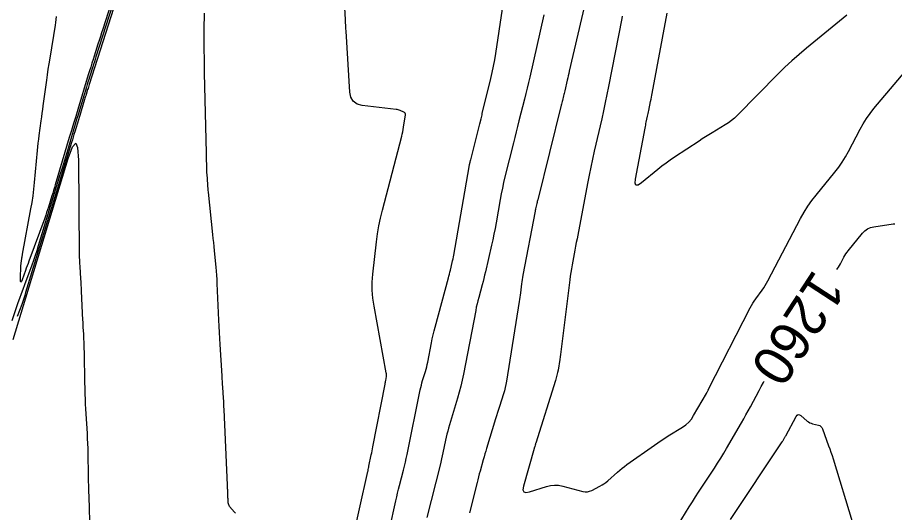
# Model space of a CAD drawing. Extents: x 658976 to 668726, y 639543 to 647196.
# Drawn here: x 661560 to 661691.9, y 641060.1 to 641134.6 of the extents above; entities that cross this region are included whole.
import ezdxf

# ---------------------------------------------------------------- set-up
doc = ezdxf.new("R2010")
doc.units = 0
for name, color, linetype in [('Ex_Contour Labels', 7, 'Continuous'), ('Ex_Major Contours', 7, 'Continuous'), ('Ex_Minor Contours', 7, 'Continuous')]:
    doc.layers.add(name, color=color, linetype=linetype)

msp = doc.modelspace()

# ---------------------------------------------------------------- linework, layer by layer
at = {"layer": 'Ex_Major Contours'}
for points in [[(661645.55, 641137.76), (661642.97, 641126.54), (661642.89, 641126.21), (661642.81, 641125.87), (661642.74, 641125.54), (661642.66, 641125.21), (661642.29, 641123.58), (661642.25, 641123.4), (661642.21, 641123.22), (661642.16, 641123.04), (661642.12, 641122.86), (661641.94, 641122.14), (661641.89, 641121.97), (661641.85, 641121.79), (661641.8, 641121.61), (661641.76, 641121.43), (661638.23, 641107.21), (661638.19, 641107.07), (661638.16, 641106.93), (661638.13, 641106.78), (661638.09, 641106.64), (661637.91, 641105.85), (661637.9, 641105.82), (661637.9, 641105.79), (661637.89, 641105.76), (661637.89, 641105.73), (661637.86, 641105.58), (661637.84, 641105.49), (661636.01, 641095.86), (661635.95, 641095.53), (661635.9, 641095.2), (661635.85, 641094.87), (661635.8, 641094.54), (661635.64, 641093.21), (661635.6, 641092.87), (661635.55, 641092.54), (661635.5, 641092.21), (661635.45, 641091.88), (661633.52, 641079.92), (661633.44, 641079.43), (661633.33, 641078.95), (661633.21, 641078.47), (661633.07, 641078), (661632.48, 641076.11), (661632.33, 641075.64), (661632.18, 641075.17), (661632.03, 641074.69), (661631.89, 641074.22), (661630.54, 641069.8), (661630.41, 641069.38), (661630.29, 641068.95), (661630.16, 641068.52), (661630.04, 641068.09), (661629.55, 641066.37), (661629.44, 641065.94), (661629.32, 641065.51), (661629.21, 641065.07), (661629.1, 641064.64), (661627.97, 641060.08)], [(661559.33, 641086.19), (661567.64, 641113.39), (661568.28, 641115.17), (661568.75, 641115.73), (661569.04, 641115.06), (661569.15, 641113.17), (661569.28, 641099.04), (661569.29, 641098.57), (661569.31, 641098.11), (661569.33, 641097.64), (661569.35, 641097.18), (661569.48, 641095.32), (661569.51, 641094.85), (661569.54, 641094.39), (661569.56, 641093.92), (661569.58, 641093.46), (661569.79, 641089.09), (661569.8, 641088.83), (661569.81, 641088.56), (661569.83, 641088.3), (661569.84, 641088.03), (661569.91, 641086.97), (661569.92, 641086.7), (661569.93, 641086.44), (661569.94, 641086.17), (661569.95, 641085.9), (661570.13, 641077.95), (661570.15, 641077.21), (661570.18, 641076.46), (661570.22, 641075.72), (661570.26, 641074.98), (661570.45, 641072.01), (661570.49, 641071.26), (661570.52, 641070.52), (661570.55, 641069.78), (661570.57, 641069.03), (661570.62, 641065.73), (661570.64, 641064.93), (661570.66, 641064.13), (661570.68, 641063.33), (661570.7, 641062.53), (661570.85, 641057.04)], [(661683.21, 641096.69), (661683.31, 641096.84), (661683.46, 641097.08), (661683.61, 641097.32), (661683.75, 641097.58), (661684.28, 641098.59), (661684.42, 641098.84), (661684.57, 641099.08), (661684.74, 641099.32), (661684.91, 641099.54), (661687.09, 641102.18), (661687.44, 641102.54), (661687.84, 641102.82), (661688.28, 641103.02), (661688.77, 641103.14), (661691.67, 641103.58), (661691.76, 641103.59), (661691.84, 641103.6), (661691.92, 641103.6)], [(661658.26, 641056.46), (661661.02, 641061.01), (661661.48, 641061.75), (661661.94, 641062.49), (661662.41, 641063.22), (661662.89, 641063.95), (661664.81, 641066.84), (661665.28, 641067.57), (661665.75, 641068.3), (661666.2, 641069.05), (661666.64, 641069.79), (661668.86, 641073.66), (661669.2, 641074.26), (661669.54, 641074.86), (661669.87, 641075.46), (661670.2, 641076.06), (661671.52, 641078.49), (661671.85, 641079.09), (661672.17, 641079.7), (661672.29, 641079.93)]]:
    msp.add_lwpolyline(points, dxfattribs=at)
at = {"layer": 'Ex_Minor Contours'}
for points in [[(661580.99, 641156.54), (661570.78, 641124.53), (661570.72, 641124.34), (661570.66, 641124.15), (661570.6, 641123.97), (661570.54, 641123.78), (661570.3, 641123.04), (661570.25, 641122.85), (661570.19, 641122.66), (661570.13, 641122.48), (661570.07, 641122.29), (661569.56, 641120.59), (661569.46, 641120.25), (661569.35, 641119.9), (661569.25, 641119.56), (661569.15, 641119.21), (661568.62, 641117.45), (661568.49, 641117.04), (661568.37, 641116.63), (661568.25, 641116.22), (661568.12, 641115.82), (661561.22, 641093.23), (661561.08, 641092.79), (661560.94, 641092.34), (661560.78, 641091.9), (661560.63, 641091.46), (661559.96, 641089.64)], [(661578.27, 641148.98), (661571.8, 641128.71), (661571.68, 641128.33), (661571.56, 641127.95), (661571.44, 641127.57), (661571.32, 641127.19), (661570.83, 641125.67), (661570.71, 641125.29), (661570.59, 641124.91), (661570.47, 641124.53), (661570.36, 641124.15), (661569.32, 641120.69), (661569.1, 641119.99), (661568.89, 641119.29), (661568.68, 641118.58), (661568.47, 641117.88), (661567.39, 641114.29), (661567.14, 641113.46), (661566.89, 641112.63), (661566.64, 641111.79), (661566.38, 641110.96), (661563.12, 641100.27), (661562.89, 641099.54), (661562.65, 641098.81), (661562.4, 641098.09), (661562.14, 641097.37), (661561.04, 641094.39), (661560.8, 641093.72), (661560.55, 641093.05), (661560.31, 641092.37), (661560.07, 641091.7), (661559.12, 641089.01)], [(661615.92, 641057.57), (661616.89, 641061.9), (661617.02, 641062.49), (661617.16, 641063.07), (661617.3, 641063.65), (661617.45, 641064.23), (661618.04, 641066.54), (661618.18, 641067.12), (661618.32, 641067.7), (661618.45, 641068.29), (661618.58, 641068.87), (661620.57, 641078.58), (661620.65, 641078.93), (661620.73, 641079.29), (661620.82, 641079.64), (661620.92, 641079.99), (661621.34, 641081.38), (661621.44, 641081.72), (661621.53, 641082.08), (661621.61, 641082.43), (661621.68, 641082.78), (661622.24, 641085.67), (661622.36, 641086.27), (661622.49, 641086.86), (661622.63, 641087.46), (661622.79, 641088.05), (661624.81, 641095.44), (661624.88, 641095.72), (661624.96, 641096.01), (661625.03, 641096.3), (661625.1, 641096.59), (661625.36, 641097.74), (661625.43, 641098.02), (661625.49, 641098.31), (661625.54, 641098.6), (661625.6, 641098.89), (661627.9, 641112.14), (661627.92, 641112.23), (661627.94, 641112.32), (661627.96, 641112.41), (661627.98, 641112.51), (661628.07, 641112.87), (661628.09, 641112.96), (661628.11, 641113.05), (661628.14, 641113.14), (661628.16, 641113.23), (661629.33, 641117.84), (661629.38, 641118.04), (661629.43, 641118.23), (661629.47, 641118.43), (661629.52, 641118.62), (661629.71, 641119.4), (661629.75, 641119.6), (661629.8, 641119.8), (661629.85, 641119.99), (661629.89, 641120.19), (661631.18, 641125.43), (661631.4, 641126.37), (661631.6, 641127.32), (661631.77, 641128.27), (661631.92, 641129.22), (661634.07, 641143.7)], [(661575.54, 641141.42), (661572.83, 641132.9), (661572.64, 641132.33), (661572.46, 641131.75), (661572.28, 641131.18), (661572.09, 641130.61), (661571.36, 641128.31), (661571.18, 641127.74), (661571, 641127.16), (661570.82, 641126.59), (661570.64, 641126.01), (661569.07, 641120.8), (661568.75, 641119.73), (661568.43, 641118.67), (661568.11, 641117.61), (661567.79, 641116.55), (661565.66, 641109.45), (661565.54, 641109.04), (661565.41, 641108.62), (661565.29, 641108.2), (661565.16, 641107.78), (661564.65, 641106.11), (661564.52, 641105.69), (661564.38, 641105.28), (661564.24, 641104.87), (661564.09, 641104.46), (661561.7, 641097.98), (661561.58, 641097.62), (661561.45, 641097.27), (661561.32, 641096.92), (661561.19, 641096.57), (661560.69, 641095.15), (661560.58, 641094.89), (661560.51, 641094.81), (661560.47, 641094.91), (661560.46, 641095.2), (661560.52, 641097.39), (661560.53, 641097.53), (661560.54, 641097.66), (661560.56, 641097.8), (661560.58, 641097.94), (661560.67, 641098.48), (661560.7, 641098.62), (661560.72, 641098.75), (661560.75, 641098.89), (661560.77, 641099.03), (661562.02, 641105.83), (661562.19, 641106.81), (661562.34, 641107.8), (661562.46, 641108.79), (661562.56, 641109.78), (661562.99, 641114.62), (661563.05, 641115.18), (661563.11, 641115.74), (661563.18, 641116.3), (661563.25, 641116.86), (661563.57, 641119.1), (661563.65, 641119.66), (661563.72, 641120.22), (661563.8, 641120.78), (661563.88, 641121.34), (661564.4, 641125.19), (661564.51, 641126.01), (661564.63, 641126.84), (661564.76, 641127.67), (661564.89, 641128.49), (661565.69, 641133.46), (661565.76, 641133.9), (661565.82, 641134.34), (661565.88, 641134.79)], [(661610.18, 641055.1), (661612.69, 641066.33), (661612.71, 641066.4), (661612.72, 641066.46), (661612.74, 641066.53), (661612.75, 641066.59), (661612.8, 641066.86), (661612.83, 641066.99), (661612.85, 641067.12), (661613.19, 641068.82), (661613.26, 641069.13), (661613.32, 641069.43), (661613.38, 641069.74), (661613.44, 641070.04), (661615.28, 641079.46), (661615.31, 641079.6), (661615.33, 641079.75), (661615.36, 641079.89), (661615.38, 641080.03), (661615.47, 641080.6), (661615.48, 641080.74), (661615.49, 641080.89), (661615.48, 641081.03), (661615.46, 641081.17), (661613.61, 641091.18), (661613.43, 641092.38), (661613.34, 641093.58), (661613.34, 641094.79), (661613.43, 641096), (661613.97, 641100.86), (661614.13, 641102.06), (661614.33, 641103.27), (661614.57, 641104.46), (661614.86, 641105.64), (661617.77, 641116.75), (661617.85, 641117.09), (661617.93, 641117.44), (661618, 641117.8), (661618.05, 641118.15), (661618.32, 641119.97), (661618.32, 641120.11), (661618.29, 641120.23), (661618.21, 641120.33), (661618.08, 641120.4), (661617.52, 641120.65), (661617.38, 641120.71), (661617.23, 641120.75), (661617.08, 641120.79), (661616.93, 641120.81), (661611.85, 641121.41), (661611.06, 641121.61), (661610.48, 641122.02), (661610.11, 641122.62), (661609.95, 641123.42), (661609.41, 641132.55), (661609.39, 641133), (661609.36, 641133.44), (661609.34, 641133.88), (661609.31, 641134.33), (661609.21, 641136.1)], [(661592.79, 641060.05), (661592.63, 641060.21), (661591.9, 641061.07), (661591.82, 641061.18), (661591.76, 641061.31), (661591.72, 641061.45), (661591.7, 641061.59), (661591.66, 641062.18), (661591.65, 641062.33), (661591.65, 641062.47), (661591.64, 641062.62), (661591.64, 641062.77), (661591.61, 641063.54), (661591.6, 641063.72), (661591.6, 641063.89), (661591.59, 641064.07), (661591.58, 641064.25), (661591.06, 641075.66), (661591.04, 641076.08), (661591.02, 641076.5), (661591, 641076.92), (661590.97, 641077.34), (661590.87, 641079.02), (661590.84, 641079.44), (661590.82, 641079.86), (661590.79, 641080.28), (661590.76, 641080.7), (661590.46, 641085.41), (661590.4, 641086.33), (661590.35, 641087.25), (661590.3, 641088.18), (661590.26, 641089.1), (661590.03, 641094.62), (661590, 641095.23), (661589.96, 641095.85), (661589.92, 641096.47), (661589.86, 641097.08), (661589.62, 641099.54), (661589.56, 641100.15), (661589.5, 641100.77), (661589.44, 641101.38), (661589.38, 641102), (661588.72, 641108.35), (661588.69, 641108.64), (661588.66, 641108.93), (661588.64, 641109.22), (661588.61, 641109.51), (661588.5, 641111.04), (661588.49, 641111.14), (661588.49, 641111.24), (661588.48, 641111.35), (661588.48, 641111.45), (661588.46, 641111.85), (661588.46, 641111.95), (661588.46, 641112.05), (661588.46, 641112.15), (661588.46, 641112.25), (661588.44, 641113.4), (661588.44, 641113.62), (661588.44, 641113.84), (661588.43, 641114.07), (661588.43, 641114.29), (661588.14, 641126.24), (661588.12, 641127.07), (661588.11, 641127.89), (661588.1, 641128.71), (661588.09, 641129.53), (661588.08, 641132.83), (661588.08, 641133.65), (661588.1, 641134.47), (661588.12, 641135.29)], [(661639.16, 641135.03), (661637.03, 641125.67), (661636.84, 641124.84), (661636.64, 641124.01), (661636.44, 641123.19), (661636.23, 641122.36), (661635.4, 641119.07), (661635.19, 641118.24), (661634.98, 641117.42), (661634.78, 641116.59), (661634.57, 641115.77), (661633.3, 641110.66), (661633.1, 641109.8), (661632.91, 641108.95), (661632.74, 641108.08), (661632.58, 641107.22), (661631.97, 641103.71), (661631.81, 641102.87), (661631.65, 641102.03), (661631.47, 641101.19), (661631.29, 641100.36), (661630.36, 641096.34), (661630.24, 641095.86), (661630.12, 641095.37), (661630, 641094.89), (661629.87, 641094.41), (661629.35, 641092.49), (661629.22, 641092.01), (661629.1, 641091.52), (661628.99, 641091.04), (661628.9, 641090.55), (661627.06, 641080.97), (661626.87, 641080.05), (661626.66, 641079.14), (661626.42, 641078.23), (661626.17, 641077.33), (661624.83, 641072.86), (661624.7, 641072.4), (661624.57, 641071.94), (661624.46, 641071.47), (661624.36, 641071.01), (661623.98, 641069.14), (661623.88, 641068.67), (661623.77, 641068.2), (661623.66, 641067.74), (661623.55, 641067.27), (661621.54, 641059.41)], [(661650.95, 641134.81), (661650.89, 641134.5), (661648.89, 641124.27), (661648.64, 641123.05), (661648.39, 641121.83), (661648.13, 641120.61), (661647.85, 641119.4), (661646.73, 641114.54), (661646.46, 641113.33), (661646.2, 641112.11), (661645.95, 641110.89), (661645.71, 641109.67), (661644.24, 641101.89), (661644.14, 641101.32), (661644.03, 641100.76), (661643.93, 641100.2), (661643.82, 641099.64), (661643.39, 641097.39), (661643.29, 641096.83), (661643.2, 641096.27), (661643.11, 641095.7), (661643.04, 641095.14), (661641.76, 641084.73), (661641.7, 641084.34), (661641.65, 641083.94), (661641.59, 641083.55), (661641.53, 641083.15), (661641.28, 641081.58), (661641.21, 641081.19), (661641.12, 641080.8), (661641.02, 641080.42), (661640.91, 641080.03), (661637.93, 641070.58), (661637.91, 641070.51), (661637.89, 641070.45), (661637.87, 641070.38), (661637.85, 641070.32), (661637.77, 641070.05), (661637.75, 641069.99), (661637.73, 641069.92), (661637.71, 641069.86), (661637.69, 641069.79), (661636.09, 641064.1), (661636.01, 641063.57), (661636.14, 641063.25), (661636.46, 641063.14), (661636.99, 641063.24), (661639.53, 641064.06), (661640.14, 641064.21), (661640.75, 641064.27), (661641.37, 641064.25), (661641.99, 641064.13), (661645.03, 641063.33), (661645.36, 641063.27), (661645.7, 641063.28), (661646.02, 641063.34), (661646.34, 641063.47), (661647.59, 641064.12), (661647.9, 641064.29), (661648.19, 641064.48), (661648.48, 641064.68), (661648.75, 641064.91), (661650.24, 641066.23), (661650.58, 641066.53), (661650.93, 641066.81), (661651.28, 641067.09), (661651.65, 641067.35), (661655.77, 641070.28), (661656.29, 641070.64), (661656.81, 641070.99), (661657.33, 641071.33), (661657.86, 641071.66), (661659.98, 641072.98), (661660.49, 641073.33), (661660.94, 641073.74), (661661.33, 641074.2), (661661.67, 641074.72), (661663.6, 641078.07), (661663.63, 641078.12), (661663.66, 641078.17), (661663.68, 641078.22), (661663.71, 641078.27), (661663.82, 641078.47), (661663.85, 641078.52), (661663.87, 641078.58), (661663.9, 641078.63), (661663.93, 641078.68), (661670.17, 641090.93), (661670.36, 641091.28), (661670.57, 641091.63), (661670.79, 641091.97), (661671.02, 641092.31), (661671.97, 641093.62), (661672.21, 641093.96), (661672.43, 641094.3), (661672.63, 641094.65), (661672.83, 641095), (661677.76, 641104.41), (661678.27, 641105.33), (661678.83, 641106.22), (661679.43, 641107.08), (661680.08, 641107.91), (661682.92, 641111.36), (661683.5, 641112.09), (661684.03, 641112.86), (661684.53, 641113.66), (661684.98, 641114.48), (661686.71, 641117.82), (661687.16, 641118.64), (661687.66, 641119.43), (661688.2, 641120.19), (661688.78, 641120.93), (661695.42, 641128.81)], [(661684.69, 641134.98), (661678.64, 641130.01), (661677.54, 641129.08), (661676.46, 641128.12), (661675.41, 641127.14), (661674.39, 641126.13), (661668.21, 641119.87), (661667.8, 641119.47), (661667.36, 641119.11), (661666.9, 641118.77), (661666.42, 641118.46), (661664.44, 641117.27), (661663.95, 641116.97), (661663.46, 641116.66), (661662.98, 641116.35), (661662.5, 641116.04), (661658.82, 641113.62), (661658.16, 641113.17), (661657.52, 641112.71), (661656.89, 641112.24), (661656.28, 641111.75), (661653.84, 641109.74), (661653.33, 641109.4), (661653, 641109.38), (661652.86, 641109.68), (661652.91, 641110.29), (661654.37, 641117.99), (661654.41, 641118.21), (661654.46, 641118.44), (661654.5, 641118.66), (661654.55, 641118.88), (661654.76, 641119.76), (661654.81, 641119.98), (661654.85, 641120.2), (661654.9, 641120.42), (661654.95, 641120.65), (661655.21, 641122.01), (661655.27, 641122.32), (661655.33, 641122.62), (661655.39, 641122.92), (661655.44, 641123.22), (661657.69, 641135.27)], [(661667.21, 641059.07), (661674.99, 641070.78), (661675.04, 641070.85), (661675.09, 641070.93), (661675.13, 641071), (661675.18, 641071.08), (661675.35, 641071.38), (661675.39, 641071.46), (661675.44, 641071.53), (661675.48, 641071.61), (661675.52, 641071.69), (661677.09, 641074.58), (661677.24, 641074.78), (661677.41, 641074.87), (661677.59, 641074.85), (661677.8, 641074.72), (661678.76, 641073.91), (661678.94, 641073.77), (661679.13, 641073.66), (661679.34, 641073.57), (661679.55, 641073.5), (661680.44, 641073.29), (661680.64, 641073.22), (661680.81, 641073.1), (661680.94, 641072.95), (661681.04, 641072.76), (661681.97, 641070.2), (661682.15, 641069.71), (661682.32, 641069.21), (661682.49, 641068.7), (661682.64, 641068.2), (661685.52, 641058.78)]]:
    msp.add_lwpolyline(points, dxfattribs=at)

# ---------------------------------------------------------------- texts
at = {"layer": 'Ex_Contour Labels'}
msp.add_text('1260', height=6, rotation=236.9152, dxfattribs=at).set_placement((661679.78, 641096.93))

doc.saveas('drawing.dxf')
